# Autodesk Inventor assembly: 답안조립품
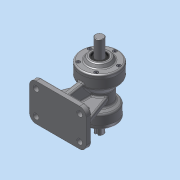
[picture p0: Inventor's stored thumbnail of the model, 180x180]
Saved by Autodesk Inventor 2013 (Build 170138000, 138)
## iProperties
Created: 2015-08
Part Number: 답안조립품
Document SubType Name: Assembly
Designer: dgall
Author: dgall
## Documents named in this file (10)
- C:\Users\dgall\Desktop\450805V1038\답안조립품.iam
- C:\Users\dgall\Desktop\450805V1038\본체.ipt
- C:\Users\dgall\Desktop\450805V1038\뒤커버.ipt
- C:\Users\dgall\Desktop\450805V1038\앞커버.ipt
- C:\Users\dgall\Desktop\450805V1038\M4x0.5.ipt
- C:\Users\dgall\Desktop\450805V1038\축.ipt
- C:\Users\dgall\Desktop\450805V1038\베어링 6205.ipt
- C:\Users\dgall\Desktop\450805V1038\베어링 6203.ipt
- C:\Users\dgall\Desktop\450805V1038\오일실 .ipt
- 오일실 .ipt
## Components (10 placed, 1 different names)
1. M4x0.5:1
2. M4x0.5:3
3. M4x0.5:4
4. M4x0.5:5
5. M4x0.5:6
6. M4x0.5:2
7. M4x0.5:7
8. M4x0.5:8
9. M4x0.5:9
10. M4x0.5:10
